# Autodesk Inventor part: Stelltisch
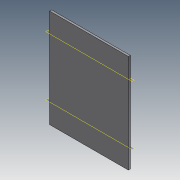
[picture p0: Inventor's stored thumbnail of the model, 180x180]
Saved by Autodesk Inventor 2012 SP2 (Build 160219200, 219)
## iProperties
Created: 2012-10
Part Number: Stelltisch
Material: Standard
Description: =<BEZEICHNUNG DEUTSCH>
Document SubType Name: Modeling
Designer: Massmann
Density: 1 g/cm^3
Author: Massmann
IdentNr: =<SAP MATERIALNUMMER>
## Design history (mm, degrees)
sketch "Skizze1"
  geometry: L1 (-200, 5)-(200, 5); L2 (200, 5)-(200, -5); L3 (200, -5)-(-200, -5); L4 (-200, -5)-(-200, 5); 3 further points
  constraints: 8 end point, 2 midpoint, 2 parallel, 1 horizontal, 1 horizontal alignment, 1 perpendicular, 1 vertical alignment
  dimensions: "d0" = 400 distance between parallel lines of L2 L4; "d1" = 10 distance of L3.end L1.start
extrude "Extrusion1" new body sketch "Skizze1" stored distance "d2" = 500; taper "d3" = 0 deg
workplane "Arbeitsebene1"
workplane "Arbeitsebene2"
node "Volumenkörper1"
node "Volumenkörpern"
node "Oberflächenkörpern"
other parameters: "G_L" = 0.1 [user parameter], "G_B" = 0.1 [user parameter]
